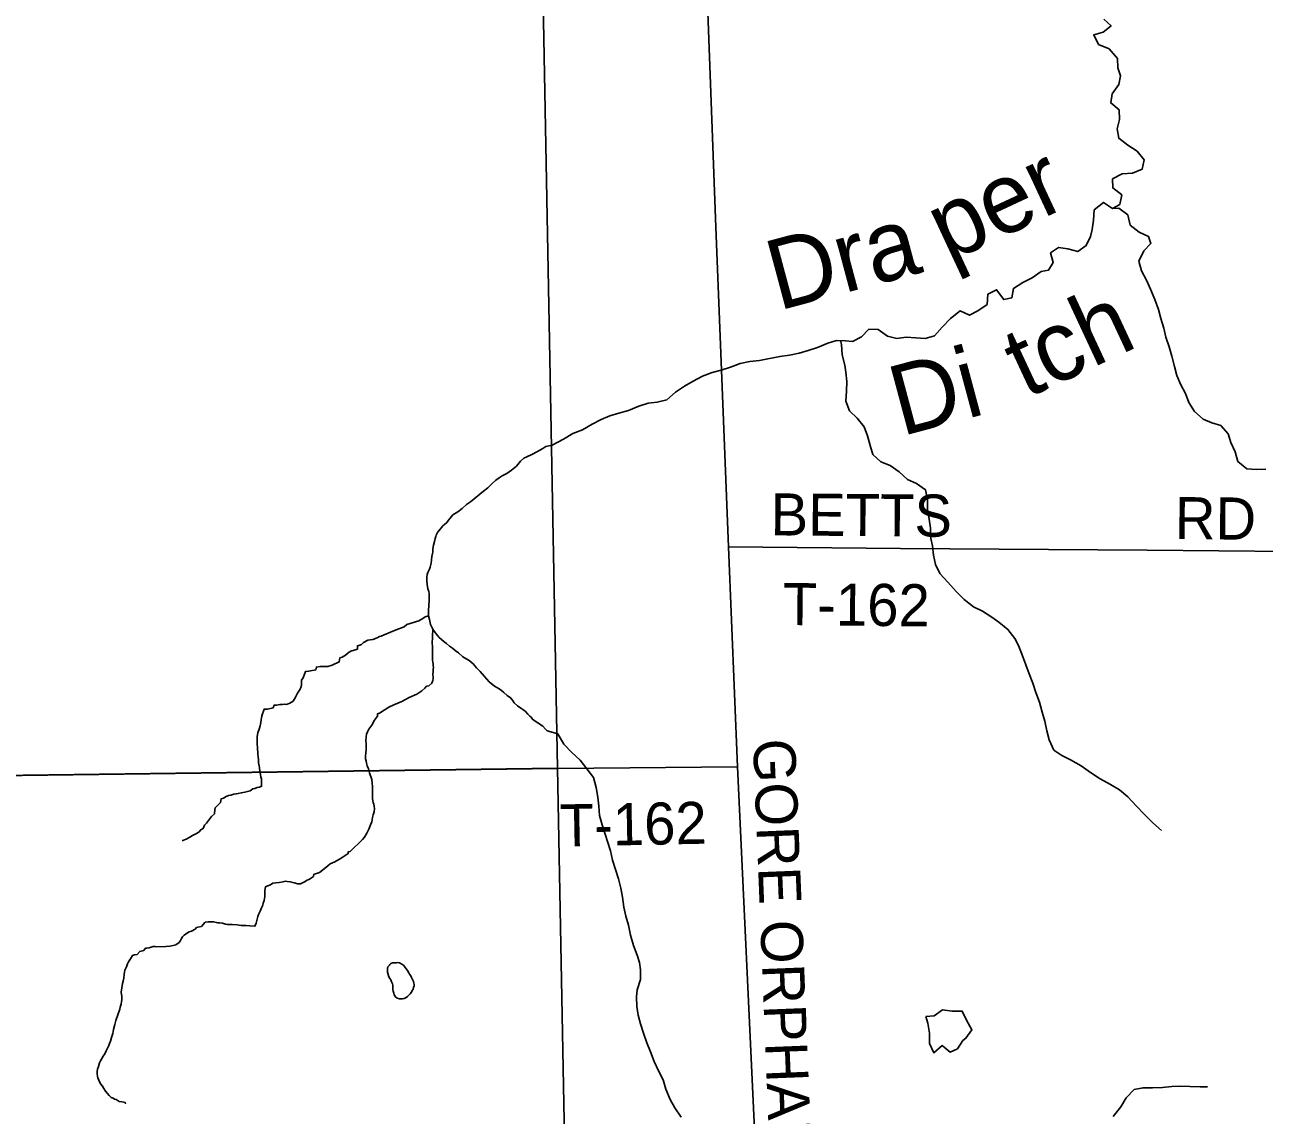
# Model space of a CAD drawing. Extents: x 0 to 34, y 0 to 22.
# Drawn here: x 6.388 to 8.061, y 14.914 to 16.386 of the extents above; entities that cross this region are included whole.
import ezdxf

# ---------------------------------------------------------------- set-up
doc = ezdxf.new("R2010")
doc.units = 0
for name, color, linetype in [('GM_X_Corporation', 7, 'Continuous'), ('GM_X_County_Road', 7, 'Continuous'), ('GM_X_County_Road_Text', 7, 'Continuous'), ('GM_X_Minor_Lake', 7, 'Continuous'), ('GM_X_Minor_River', 7, 'Continuous'), ('GM_X_Minor_River_Text', 7, 'Continuous'), ('GM_X_Township_Road', 7, 'Continuous'), ('GM_X_Township_Road_Text', 7, 'Continuous')]:
    doc.layers.add(name, color=color, linetype=linetype)

msp = doc.modelspace()

# ---------------------------------------------------------------- linework, layer by layer
at = {"layer": 'GM_X_Corporation'}
for points in [[(7.0838, 16.6084), (7.1072, 15.3824), (7.118, 14.8105), (7.1215, 14.6514), (7.1267, 14.4123), (7.1269, 14.4049), (7.1335, 14.1), (8.9, 14.1), (8.9, 20.9)], [(2.1, 20.3879), (2.1, 14.1), (7.1335, 14.1), (7.1269, 14.4049), (7.1267, 14.4123), (7.1215, 14.6514), (7.118, 14.8105), (7.1072, 15.3824), (7.0838, 16.6084)], [(2.1, 20.3879), (2.1, 15.3574), (2.6127, 15.3592), (3.4135, 15.3624), (4.1534, 15.3654), (4.1554, 15.3654), (5.1944, 15.3696), (5.8313, 15.3671), (6.0415, 15.3685), (7.1072, 15.3824), (7.0838, 16.6084)]]:
    msp.add_lwpolyline(points, dxfattribs=at)
for points in [[(8.9, 14.638), (8.9, 19.8484), (8.3424, 19.8533), (7.6795, 19.8561), (7.3272, 19.8568), (7.1717, 19.8568), (7.0046, 19.8599), (7.0077, 19.6756), (7.0107, 19.4664), (7.0305, 18.5559), (7.0429, 18.0629), (7.0494, 17.8247), (7.0577, 17.449), (7.0649, 17.2134), (7.0651, 17.204), (7.0717, 16.9849), (7.0838, 16.6084), (7.1072, 15.3824), (7.118, 14.8105), (7.1215, 14.6514), (7.384, 14.6494), (8.0793, 14.6442), (8.8452, 14.6384)], [(2.1, 15.3574), (2.1, 14.1), (7.1335, 14.1), (7.1269, 14.4049), (7.1267, 14.4123), (7.1215, 14.6514), (7.118, 14.8105), (7.1072, 15.3824), (6.0415, 15.3685), (5.8313, 15.3671), (5.1944, 15.3696), (4.1554, 15.3654), (4.1534, 15.3654), (3.4135, 15.3624), (2.6127, 15.3592)]]:
    msp.add_lwpolyline(points, close=True, dxfattribs=at)
at = {"layer": 'GM_X_County_Road'}
for p, q in [((7.3501, 15.3842), (7.3381, 15.6814)), ((7.3839, 14.6558), (7.3501, 15.3842))]:
    msp.add_line(p, q, dxfattribs=at)
msp.add_lwpolyline([(7.3381, 15.6814), (7.321, 16.1128), (7.3068, 16.488), (7.2978, 16.731), (7.2856, 17.0713), (7.2822, 17.2029)], dxfattribs=at)
at = {"layer": 'GM_X_Minor_Lake'}
for points in [[(6.8807, 15.1175), (6.8799, 15.1165), (6.878, 15.1143), (6.8772, 15.112), (6.8772, 15.1097), (6.8772, 15.1078), (6.8773, 15.107)], [(6.8773, 15.107), (6.8772, 15.1078), (6.8772, 15.1097), (6.8772, 15.112), (6.878, 15.1143), (6.8799, 15.1165), (6.8807, 15.1175)], [(6.8773, 15.107), (6.8794, 15.1006), (6.8806, 15.0986), (6.8817, 15.0967), (6.8828, 15.0941), (6.8843, 15.0914), (6.8847, 15.0895), (6.8847, 15.0872), (6.8847, 15.0838), (6.885, 15.0815), (6.8858, 15.0788), (6.8865, 15.0762), (6.888, 15.0735), (6.8907, 15.072), (6.8937, 15.0712), (6.8956, 15.0712), (6.8976, 15.0712), (6.8998, 15.0715), (6.9025, 15.073), (6.9044, 15.0741), (6.9079, 15.0779), (6.9098, 15.0802), (6.9106, 15.0821), (6.9121, 15.084), (6.9125, 15.0863), (6.9133, 15.0885), (6.9133, 15.0904), (6.9129, 15.0923), (6.9125, 15.0942), (6.9114, 15.0973), (6.9099, 15.1), (6.9088, 15.1019), (6.9072, 15.1042), (6.9061, 15.1061), (6.9046, 15.1091), (6.9027, 15.1114), (6.9012, 15.1133), (6.8993, 15.116), (6.897, 15.1179), (6.8936, 15.1195), (6.8913, 15.1199), (6.8898, 15.1196)], [(6.8898, 15.1196), (6.8913, 15.1199), (6.8936, 15.1195), (6.897, 15.1179), (6.8993, 15.116), (6.9012, 15.1133), (6.9027, 15.1114), (6.9046, 15.1091), (6.9061, 15.1061), (6.9072, 15.1042), (6.9088, 15.1019), (6.9099, 15.1), (6.9114, 15.0973), (6.9125, 15.0942), (6.9129, 15.0923), (6.9133, 15.0904), (6.9133, 15.0885), (6.9125, 15.0863), (6.9121, 15.084), (6.9106, 15.0821), (6.9098, 15.0802), (6.9079, 15.0779), (6.9044, 15.0741), (6.9025, 15.073), (6.8998, 15.0715), (6.8976, 15.0712), (6.8956, 15.0712), (6.8937, 15.0712), (6.8907, 15.072), (6.888, 15.0735), (6.8865, 15.0762), (6.8858, 15.0788), (6.885, 15.0815), (6.8847, 15.0838), (6.8847, 15.0872), (6.8847, 15.0895), (6.8843, 15.0914), (6.8828, 15.0941), (6.8817, 15.0967), (6.8806, 15.0986), (6.8794, 15.1006), (6.8773, 15.107)], [(6.8898, 15.1196), (6.8841, 15.1195), (6.8818, 15.1188), (6.8807, 15.1175)], [(6.8807, 15.1175), (6.8818, 15.1188), (6.8841, 15.1195), (6.8898, 15.1196)], [(7.6545, 15.0148), (7.6584, 15.0178), (7.6665, 15.029), (7.6591, 15.0421), (7.6536, 15.0543), (7.6398, 15.0542), (7.6269, 15.0563), (7.6154, 15.0481), (7.6043, 15.0471)], [(7.6545, 15.0148), (7.6584, 15.0178), (7.6665, 15.029), (7.6591, 15.0421), (7.6536, 15.0543), (7.6398, 15.0542), (7.6269, 15.0563), (7.6154, 15.0481), (7.6043, 15.0471)], [(7.6043, 15.0471), (7.6069, 15.0383), (7.6094, 15.0246), (7.6095, 15.0109), (7.6151, 14.9983), (7.6266, 15.008), (7.6372, 14.9991), (7.6471, 15.0035), (7.6545, 15.0148)], [(7.6043, 15.0471), (7.6069, 15.0383), (7.6094, 15.0246), (7.6095, 15.0109), (7.6151, 14.9983), (7.6266, 15.008), (7.6372, 14.9991), (7.6471, 15.0035), (7.6545, 15.0148)]]:
    msp.add_lwpolyline(points, dxfattribs=at)
at = {"layer": 'GM_X_Minor_River'}
for points in [[(7.8563, 16.138), (7.8663, 16.1436), (7.8691, 16.1564), (7.8567, 16.1658), (7.8565, 16.1779), (7.8695, 16.185), (7.8832, 16.1859), (7.8966, 16.191), (7.8991, 16.2039), (7.8897, 16.2155), (7.8769, 16.2236), (7.8648, 16.2329), (7.8627, 16.2455), (7.866, 16.258), (7.8654, 16.2713), (7.8541, 16.2806), (7.8558, 16.2928), (7.8651, 16.3052), (7.8672, 16.3169), (7.8635, 16.328), (7.8633, 16.3406), (7.8517, 16.3537), (7.8377, 16.3596), (7.831, 16.3723), (7.8436, 16.3762), (7.8544, 16.3844), (7.8446, 16.3937)], [(7.0998, 15.8184), (7.1153, 15.8264), (7.1279, 15.8342), (7.1406, 15.8393), (7.1536, 15.8467), (7.1659, 15.853), (7.1778, 15.8582), (7.19, 15.8618), (7.203, 15.8654), (7.2168, 15.8713), (7.2294, 15.8752), (7.2416, 15.8766), (7.2546, 15.8798), (7.2665, 15.8899), (7.2785, 15.8981), (7.2904, 15.9051), (7.303, 15.9118), (7.316, 15.9165), (7.3279, 15.9198), (7.3405, 15.9238), (7.3535, 15.9289), (7.3669, 15.9313), (7.3798, 15.933), (7.4073, 15.938), (7.4203, 15.94), (7.4333, 15.9429), (7.4455, 15.9465), (7.4581, 15.9505), (7.4719, 15.956), (7.4838, 15.96), (7.4959, 15.9594), (7.5054, 15.9585), (7.5177, 15.9648), (7.5274, 15.9753), (7.5399, 15.9747), (7.5524, 15.9658), (7.5653, 15.9626), (7.5779, 15.9643), (7.5908, 15.9633), (7.6033, 15.9624), (7.616, 15.966), (7.6264, 15.978), (7.6376, 15.9896), (7.6507, 15.9997), (7.6632, 15.9942), (7.6747, 15.9997), (7.687, 16.0086), (7.6883, 16.0223), (7.6998, 16.0282), (7.7095, 16.0151), (7.7206, 16.0176), (7.7227, 16.0301), (7.7354, 16.0379), (7.748, 16.0442), (7.7603, 16.0528), (7.7702, 16.0549), (7.7761, 16.0651), (7.7728, 16.0781), (7.7836, 16.0855), (7.7961, 16.0834), (7.8094, 16.0798), (7.821, 16.088), (7.8268, 16.1), (7.8289, 16.1095), (7.8306, 16.1224), (7.8315, 16.1361), (7.8442, 16.1462), (7.8563, 16.138)], [(7.8563, 16.138), (7.8651, 16.1386), (7.8771, 16.1293), (7.8803, 16.1156), (7.8924, 16.1059), (7.9049, 16.1004), (7.9082, 16.0908), (7.8989, 16.0807), (7.8922, 16.0671), (7.8955, 16.0538), (7.9022, 16.0411), (7.9077, 16.0289), (7.9136, 16.0151), (7.9187, 16.0017), (7.9216, 15.9895), (7.9256, 15.9765), (7.9285, 15.9643), (7.9329, 15.9513), (7.9365, 15.9387), (7.9401, 15.9249), (7.9434, 15.9127), (7.9482, 15.9009), (7.9552, 15.8882), (7.9596, 15.8763), (7.9671, 15.8641), (7.9787, 15.8536), (7.9905, 15.8485), (8.0026, 15.8449), (8.0124, 15.8337), (8.0164, 15.8219), (8.0219, 15.8096), (8.0255, 15.7966), (8.0376, 15.7866), (8.0505, 15.7856), (8.0635, 15.7862)], [(7.4891, 15.9597), (7.4905, 15.9542), (7.4915, 15.9405), (7.4951, 15.9267), (7.4965, 15.9172), (7.4975, 15.9043), (7.4973, 15.8913), (7.4963, 15.8777), (7.5011, 15.865), (7.5116, 15.855), (7.521, 15.8434), (7.5254, 15.8312), (7.5294, 15.8182), (7.533, 15.806), (7.5435, 15.796), (7.556, 15.7912), (7.5685, 15.7826), (7.5794, 15.7722), (7.5919, 15.7667), (7.6039, 15.7582), (7.6068, 15.7452), (7.6066, 15.7315), (7.6087, 15.7185), (7.6108, 15.7063), (7.611, 15.6923), (7.6132, 15.6827), (7.6149, 15.6698), (7.6174, 15.6572), (7.6233, 15.6453), (7.6342, 15.6337), (7.6454, 15.621), (7.6559, 15.6102), (7.6687, 15.6001), (7.6808, 15.5942), (7.6933, 15.5861), (7.7031, 15.5795), (7.7152, 15.5698), (7.7245, 15.5575), (7.7297, 15.5479), (7.7348, 15.5341), (7.7396, 15.5219), (7.744, 15.51), (7.7488, 15.497), (7.7528, 15.4844), (7.758, 15.4714), (7.7616, 15.458), (7.7652, 15.4458), (7.7677, 15.4328), (7.771, 15.4206), (7.7772, 15.4068), (7.7882, 15.3995), (7.7999, 15.3936), (7.8139, 15.3858), (7.8267, 15.3768), (7.8399, 15.3682), (7.8539, 15.3604), (7.866, 15.3534), (7.8769, 15.3437), (7.8885, 15.3318), (7.8998, 15.3198), (7.911, 15.3086), (7.9227, 15.2982)], [(7.0998, 15.8184), (7.0912, 15.8168), (7.087, 15.8142), (7.0801, 15.81), (7.0725, 15.8059), (7.0656, 15.8029), (7.0614, 15.801), (7.0572, 15.7969), (7.0514, 15.7901), (7.0449, 15.7848), (7.0384, 15.7803), (7.0323, 15.7773), (7.0281, 15.7746), (7.0239, 15.7712), (7.0185, 15.7663), (7.0128, 15.7611), (7.0071, 15.7565), (6.9895, 15.7422), (6.9841, 15.7384), (6.9784, 15.7331), (6.9722, 15.7286), (6.9677, 15.726), (6.9657, 15.7245), (6.9638, 15.7222), (6.9619, 15.7199), (6.96, 15.7173), (6.9577, 15.7143), (6.9546, 15.7112), (6.952, 15.7094), (6.9504, 15.7075), (6.9489, 15.7056), (6.9462, 15.7025), (6.945, 15.7007), (6.9431, 15.6972), (6.9427, 15.6953), (6.9416, 15.6927), (6.9408, 15.6885), (6.9396, 15.6836), (6.9388, 15.6786), (6.9388, 15.6741), (6.938, 15.6722), (6.9373, 15.668), (6.9369, 15.6638), (6.9365, 15.6593), (6.9357, 15.6558), (6.9349, 15.6539), (6.9341, 15.6513), (6.9318, 15.6464), (6.931, 15.6437), (6.9306, 15.6403), (6.9306, 15.6353), (6.931, 15.6304), (6.9317, 15.6247), (6.9332, 15.6209), (6.9336, 15.6182), (6.9339, 15.6152), (6.9339, 15.6106), (6.9335, 15.6068), (6.9331, 15.6037), (6.9331, 15.6003), (6.9327, 15.5973), (6.9327, 15.5912), (6.933, 15.5882), (6.9341, 15.5832), (6.9356, 15.5763), (6.9386, 15.5702), (6.9417, 15.5657), (6.9432, 15.5637), (6.9451, 15.5615), (6.9473, 15.5588), (6.9504, 15.5561), (6.9538, 15.553), (6.9572, 15.5507), (6.961, 15.5473), (6.9652, 15.5446), (6.969, 15.5415), (6.9735, 15.5381), (6.9792, 15.5327), (6.9879, 15.5277), (6.9933, 15.5235), (6.9978, 15.5181), (7.0027, 15.5128), (7.0084, 15.5063), (7.0148, 15.499), (7.0217, 15.4932), (7.0281, 15.4894), (7.0315, 15.4875), (7.0346, 15.4844), (7.0391, 15.4806), (7.0437, 15.4775), (7.046, 15.4744), (7.0486, 15.4706), (7.0528, 15.4668), (7.0573, 15.4633), (7.0615, 15.4606), (7.0638, 15.4591), (7.0668, 15.4553), (7.0695, 15.4526), (7.0714, 15.4511)], [(6.933, 15.5882), (6.9285, 15.5867), (6.925, 15.5844), (6.9197, 15.5814), (6.9036, 15.5762), (6.8998, 15.5732), (6.8926, 15.5706), (6.8845, 15.5676), (6.8784, 15.5646), (6.8727, 15.5623), (6.8689, 15.5608), (6.8666, 15.5601), (6.8635, 15.5586), (6.8578, 15.5563), (6.854, 15.5556), (6.851, 15.5552), (6.8452, 15.5519), (6.8422, 15.5496), (6.8387, 15.5481), (6.8368, 15.5477), (6.8368, 15.5432), (6.828, 15.5402), (6.8242, 15.5383), (6.8208, 15.5349), (6.8162, 15.5323), (6.8131, 15.5312), (6.8123, 15.5258), (6.8028, 15.5217), (6.7967, 15.5199), (6.7932, 15.5199), (6.7864, 15.5195), (6.7814, 15.5188), (6.7807, 15.5154), (6.7711, 15.5132), (6.7665, 15.5128), (6.7635, 15.5045), (6.7615, 15.5011), (6.7611, 15.4969), (6.7611, 15.495), (6.7607, 15.4927), (6.7596, 15.4893), (6.7576, 15.4866), (6.7561, 15.4836), (6.7542, 15.4802), (6.7526, 15.4776), (6.75, 15.473), (6.7454, 15.47), (6.7412, 15.4685), (6.7389, 15.4689), (6.7355, 15.4685), (6.732, 15.4682), (6.7275, 15.4675), (6.7244, 15.4675), (6.7232, 15.4641), (6.7156, 15.4622), (6.7107, 15.4619), (6.7076, 15.4531), (6.7072, 15.4501), (6.7068, 15.4482), (6.7064, 15.444), (6.7056, 15.4398), (6.704, 15.4349), (6.7025, 15.4303), (6.7013, 15.425), (6.7013, 15.4178), (6.702, 15.4071), (6.7024, 15.4049), (6.7023, 15.4014), (6.7027, 15.3976), (6.7031, 15.3935), (6.7034, 15.3896), (6.7042, 15.3858), (6.7045, 15.3828), (6.7049, 15.3778), (6.706, 15.374), (6.7064, 15.3702), (6.7071, 15.3679), (6.7075, 15.366), (6.7075, 15.3638), (6.7075, 15.3615), (6.7074, 15.3581), (6.7044, 15.3569), (6.7013, 15.3562), (6.6983, 15.3551), (6.6956, 15.3547), (6.6918, 15.3517), (6.6849, 15.3502), (6.68, 15.3491), (6.6758, 15.3484), (6.6735, 15.348), (6.6697, 15.3473), (6.6659, 15.3462), (6.6628, 15.3454), (6.6594, 15.3443), (6.6559, 15.342), (6.6529, 15.3409), (6.6517, 15.336), (6.6471, 15.3311), (6.6448, 15.3288), (6.6444, 15.3265), (6.6436, 15.3208)], [(6.9386, 15.5702), (6.9378, 15.5505), (6.9381, 15.5474), (6.9381, 15.5448), (6.9381, 15.5402), (6.9381, 15.5353), (6.9381, 15.5322), (6.9384, 15.5284), (6.9388, 15.5254), (6.9392, 15.5231), (6.9392, 15.5212), (6.9395, 15.5185), (6.9391, 15.5159), (6.9391, 15.5128), (6.9387, 15.509), (6.9391, 15.5052), (6.9391, 15.5033), (6.9387, 15.501), (6.9371, 15.4972), (6.9333, 15.4938), (6.9302, 15.4931), (6.9279, 15.4904), (6.9237, 15.4867), (6.9169, 15.4825), (6.9069, 15.478), (6.8966, 15.4724), (6.8859, 15.4679), (6.8791, 15.4649), (6.8664, 15.4566), (6.8641, 15.4559), (6.8641, 15.4528), (6.8599, 15.4472), (6.8561, 15.4403), (6.8522, 15.435), (6.8503, 15.4316), (6.8491, 15.4282), (6.8484, 15.4248), (6.8483, 15.4195), (6.8487, 15.4157), (6.8487, 15.4122), (6.8487, 15.4077), (6.8482, 15.4027), (6.8475, 15.3989), (6.8478, 15.3951), (6.8486, 15.3925), (6.8489, 15.3894), (6.8501, 15.3856), (6.8516, 15.3814), (6.8531, 15.3761), (6.8561, 15.3673), (6.8568, 15.3624), (6.8572, 15.3578), (6.8571, 15.3536), (6.8571, 15.3475), (6.8571, 15.3411), (6.8582, 15.3361), (6.8589, 15.3338), (6.8593, 15.3308), (6.8597, 15.3281), (6.8593, 15.3236), (6.8581, 15.3194), (6.8573, 15.316), (6.8569, 15.3133), (6.8561, 15.3095), (6.855, 15.3072), (6.8542, 15.3046), (6.8523, 15.3), (6.8496, 15.2947), (6.8465, 15.2894), (6.8438, 15.286), (6.827, 15.2698), (6.8243, 15.2694), (6.8243, 15.2671), (6.8147, 15.2611), (6.8063, 15.2562), (6.7998, 15.2532), (6.7968, 15.2506), (6.7918, 15.2464), (6.7857, 15.2415), (6.7803, 15.2397), (6.7781, 15.2393), (6.7777, 15.2363), (6.7719, 15.2325), (6.7681, 15.2306), (6.7662, 15.2295), (6.7628, 15.2276), (6.7601, 15.2265), (6.7563, 15.2265), (6.7513, 15.2277), (6.746, 15.2292), (6.7418, 15.2296), (6.7395, 15.2297), (6.7361, 15.2289), (6.7311, 15.2282), (6.7266, 15.2275), (6.7228, 15.2271), (6.7193, 15.2249), (6.7144, 15.223)], [(7.0714, 15.4511), (7.0732, 15.4484), (7.077, 15.4457), (7.0805, 15.4438), (7.0827, 15.4422), (7.085, 15.4403), (7.0873, 15.4392), (7.0907, 15.4353), (7.093, 15.4327), (7.1073, 15.4289)], [(7.1073, 15.4289), (7.1157, 15.415), (7.1262, 15.4038), (7.1374, 15.3933), (7.1464, 15.3814), (7.1554, 15.3699), (7.159, 15.3565), (7.1615, 15.3435), (7.1628, 15.331), (7.1638, 15.3184), (7.1674, 15.3058), (7.1715, 15.2932), (7.1747, 15.2836), (7.1784, 15.271), (7.1812, 15.2581), (7.1853, 15.2455), (7.1893, 15.2332), (7.1925, 15.2203), (7.1946, 15.2081), (7.1964, 15.1947), (7.1992, 15.1825), (7.2029, 15.1707), (7.2057, 15.1569), (7.2097, 15.1432), (7.2145, 15.1302), (7.2178, 15.1203), (7.2192, 15.11), (7.219, 15.097), (7.2146, 15.083), (7.2137, 15.0735), (7.2143, 15.0606), (7.216, 15.0488), (7.2189, 15.0373), (7.2233, 15.0247), (7.2277, 15.0117), (7.2325, 14.9995), (7.2376, 14.9865), (7.2435, 14.9739), (7.2495, 14.9616), (7.2531, 14.949), (7.259, 14.9352), (7.2653, 14.9237), (7.2739, 14.9114)], [(6.6436, 15.3208), (6.6398, 15.3174), (6.6329, 15.3084), (6.6302, 15.3057), (6.6283, 15.3008), (6.6252, 15.2993), (6.6226, 15.2959), (6.6187, 15.2936), (6.6141, 15.2914), (6.6103, 15.2891), (6.6057, 15.2865), (6.6012, 15.285), (6.6, 15.285)], [(6.7144, 15.223), (6.7125, 15.2222), (6.7117, 15.2173), (6.7116, 15.2124), (6.7116, 15.2093), (6.7108, 15.204), (6.7097, 15.2002), (6.7089, 15.1975), (6.7073, 15.1938), (6.7054, 15.1896), (6.7035, 15.1858), (6.7023, 15.1824), (6.7, 15.1733), (6.6985, 15.1691), (6.6916, 15.1695), (6.6863, 15.1699), (6.6798, 15.17), (6.6745, 15.1708), (6.6676, 15.1716), (6.6615, 15.1716), (6.6585, 15.172), (6.6547, 15.1732), (6.6505, 15.1736), (6.6486, 15.1736), (6.6463, 15.174), (6.6425, 15.1752), (6.6387, 15.1752), (6.6353, 15.1752), (6.6314, 15.1745), (6.6261, 15.1688), (6.6215, 15.1677), (6.6196, 15.1673), (6.6177, 15.1651), (6.6127, 15.1624), (6.6097, 15.1613), (6.6062, 15.1594), (6.6028, 15.1568), (6.6005, 15.1549), (6.5993, 15.1523), (6.5978, 15.15), (6.5959, 15.147), (6.5917, 15.1439), (6.5882, 15.1432), (6.5833, 15.1421), (6.5783, 15.1418), (6.5661, 15.1411), (6.5638, 15.1415), (6.5608, 15.1415), (6.5581, 15.1407), (6.5555, 15.14), (6.5524, 15.1393), (6.5505, 15.1393), (6.5482, 15.1363), (6.5429, 15.1351), (6.5394, 15.131), (6.536, 15.1303), (6.5329, 15.1295), (6.5302, 15.125), (6.5279, 15.1212), (6.5264, 15.1185), (6.5248, 15.1144), (6.5229, 15.1098), (6.5217, 15.1045), (6.5213, 15.0988), (6.5205, 15.095), (6.5198, 15.0916), (6.5186, 15.0859), (6.5178, 15.0802), (6.5182, 15.0767), (6.5185, 15.0748), (6.5189, 15.0726), (6.5189, 15.0695), (6.5181, 15.0672), (6.5177, 15.0638), (6.5166, 15.0596), (6.5158, 15.057), (6.5107, 15.0418), (6.5092, 15.0365), (6.5076, 15.0297), (6.5065, 15.024), (6.5049, 15.0186), (6.5034, 15.0137), (6.5022, 15.0107), (6.501, 15.008), (6.4995, 15.0042), (6.4976, 15.0008), (6.4957, 14.9967), (6.4937, 14.9936), (6.4914, 14.9895), (6.4899, 14.9872), (6.4887, 14.9845), (6.4872, 14.9796), (6.4856, 14.9762), (6.4852, 14.9731), (6.4852, 14.9693), (6.486, 14.9667), (6.4863, 14.9644), (6.4878, 14.961), (6.4901, 14.9564), (6.4924, 14.9533), (6.4943, 14.9499)], [(6.4943, 14.9499), (6.4965, 14.9464), (6.4992, 14.943), (6.5018, 14.9403), (6.5045, 14.938), (6.5068, 14.9369), (6.509, 14.9357), (6.511, 14.9353), (6.5151, 14.9326), (6.5189, 14.9318), (6.5216, 14.9314), (6.5231, 14.9311), (6.5235, 14.9291)], [(7.8575, 14.9121), (7.8676, 14.9252), (7.875, 14.9373), (7.8855, 14.9485), (7.8977, 14.951), (7.9106, 14.9508), (7.924, 14.9514), (7.9365, 14.9527), (7.9487, 14.9529), (7.9609, 14.9527), (7.9746, 14.9521), (7.9845, 14.9524)]]:
    msp.add_lwpolyline(points, dxfattribs=at)
at = {"layer": 'GM_X_Township_Road'}
for p, q in [((7.3501, 15.3842), (7.3381, 15.6814)), ((6.0417, 15.3679), (7.1074, 15.3818)), ((7.1074, 15.3818), (7.3501, 15.3842))]:
    msp.add_line(p, q, dxfattribs=at)
msp.add_lwpolyline([(7.3381, 15.6814), (7.5702, 15.6792), (7.9034, 15.6768), (8.097, 15.6749)], dxfattribs=at)

# ---------------------------------------------------------------- texts
at = {"layer": 'GM_X_County_Road_Text'}
msp.add_text('GORE ORPHANAGE RD', height=0.056818, rotation=272.2962, dxfattribs=at).set_placement((7.3709, 15.4211))
at = {"layer": 'GM_X_Minor_River_Text'}
for s, height, rotation, p in [('per', 0.09475, 24.9985, (7.6344, 16.0647)), ('Dra', 0.09474, 14.9981, (7.4051, 15.9997)), ('tch', 0.09475, 24.9983, (7.7397, 15.8809)), ('Di', 0.09474, 14.9981, (7.5713, 15.8302))]:
    msp.add_text(s, height=height, rotation=rotation, dxfattribs=at).set_placement(p)
at = {"layer": 'GM_X_Township_Road_Text'}
for s, rotation, p in [('BETTS', 359.5509, (7.3946, 15.6967)), ('RD', 359.5064, (7.9404, 15.6917)), ('T-162', 359.4386, (7.411, 15.5757)), ('T-162', 1.1238, (7.1105, 15.2766))]:
    msp.add_text(s, height=0.05682, rotation=rotation, dxfattribs=at).set_placement(p)

doc.saveas('drawing.dxf')
